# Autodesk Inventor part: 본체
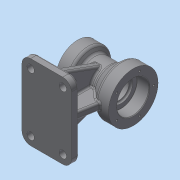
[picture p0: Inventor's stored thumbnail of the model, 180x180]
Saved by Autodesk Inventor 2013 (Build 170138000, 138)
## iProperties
Created: 2015-08
Part Number: 본체
Material: 일반
Document SubType Name: Modeling
Designer: Administrator
Density: 1 g/cm^3
Author: Administrator
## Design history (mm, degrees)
sketch "스케치1"
  geometry: L1 (0, 0)-(90, 0); L2 (0, 0)-(0, 35); L3 (0, 35)-(20, 35); L4 (20, 35)-(25.196, 26); L5 (25.196, 26)-(53.315, 26); L6 (53.315, 26)-(70, 40); L7 (70, 40)-(90, 40); L8 (90, 40)-(90, 0)
  constraints: 17 end point, 3 parallel, 2 perpendicular, 1 horizontal
  dimensions: "d0" = 90 distance of L1.start L1.end; "d2" = 70 diameter of L3 L1; "d3" = 80 diameter of L7 L1; "d4" = 60 deg angle of L5 L4; "d6" = 40 deg angle of L6 L5; "d7" = 20 distance of L6.end L7.end; "d8" = 20 distance of L2.end L3.end; "d9" = 52 diameter of L5 L1
revolve "회전1" sketch "스케치1" stored, may be unused: angle "d10" = 90 deg
node "작업 평면1"
sketch "스케치2"
  geometry: L1 (0, 61)-(80, 61); L2 (80, 61)-(80, -61); L3 (80, -61)-(0, -61); L4 (0, -61)-(0, 61); 2 further points
  constraints: 8 end point, 2 parallel, 1 coincident, 1 horizontal, 1 midpoint, 1 perpendicular, 1 vertical alignment
  dimensions: "d12" = 80 distance of L1.start L1.end; "d14" = 122 distance of L1.end L2.end
extrude "돌출1" join sketch "스케치2" distance "d15" = 12; taper "d16" = 0 deg
fillet "모깎기1" dims "d17" = 14
node "작업 평면2"
sketch "스케치6"
  geometry: L1 (-90, 61)-(-78, 61) reference; L2 (-78, 61)-(-78, -61) reference; L3 (-78, -61)-(-90, -61) reference; L4 (-90, -61)-(-90, 61) reference; L5 (-78, 51)-(-6.815, 25.091); L6 (-6.815, 25.091)-(-6.815, -25.091); L7 (-6.815, -25.091)-(-78, -51); A1 r 26 centre (0, 0) between (-6.815, 25.091) and (-6.815, -25.091) reference; 1 further point
  constraints: 6 end point, 2 point on circle, 2 point on line, 1 parallel
  dimensions: "d29" = 10 distance of L5.start L1.end; "d30" = 10 distance of L2.end L7.end; "d31" = 70 deg angle of L2 L7
extrude "돌출2" join sketch "스케치6" stored distance "d32" = 12; taper "d33" = 0 deg
sketch "스케치7"
  geometry: L1 (0, -35)-(0, 35) reference; L2 (0, 35)-(20, 35) reference; L3 (20, 35)-(25.196, 26) reference; L4 (25.196, 26)-(53.315, 26) reference; L5 (53.315, 26)-(70, 40) reference; L6 (70, 40)-(90, 40) reference; L7 (90, 40)-(90, -40) reference; L8 (90, -40)-(70, -40) reference; L9 (70, -40)-(53.315, -26) reference; L10 (53.315, -26)-(46, -26) reference; L11 (46, -26)-(46, -78) reference; L12 (46, -78)-(80, -78) reference; L13 (80, -78)-(80, -90) reference; L14 (80, -90)-(0, -90) reference; L15 (0, -90)-(0, -78) reference; L16 (0, -78)-(34, -78) reference; L17 (34, -78)-(34, -26) reference; L18 (34, -26)-(25.196, -26) reference; L19 (25.196, -26)-(20, -35) reference; L20 (20, -35)-(0, -35) reference; L21 (10, -35)-(10, -78); L22 (76.7, -40)-(70, -78); 1 further point
  constraints: 4 end point, 3 point on line, 1 midpoint, 1 perpendicular
  dimensions: "d34" = 10 distance from line of L13 L22.end; "d35" = 80 deg angle of L12 L22; "d36" = 10 distance between parallel lines of L21 L15
  node "절단 모서리 투영2"
feature "리브1" dims "d37" = 1, "d38" = 12, "d39" = 0, "d40" = 0, "d41" = 1, "d42" = 1
feature "리브2" dims "d43" = 1, "d44" = 12, "d45" = 0, "d46" = 0, "d47" = 1, "d48" = 1
sketch "스케치8"
  geometry: L1 (-30, -54)-(-30, -60); L2 (-18, -54)-(-18, -60); L3 (-47, -90)-(47, -90) reference; A1 r 26 centre (0, 0) between (-25.091, -6.815) and (-6, -25.298) reference; A2 r 6 centre (-24, -54) between (-18, -54) and (-30, -54); A3 r 6 centre (-24, -60) between (-30, -60) and (-18, -60)
  constraints: 4 end point, 4 point on circle, 4 tangent, 2 centre point, 1 vertical alignment
  dimensions: "d49" = 12 diameter of A2; "d50" = 12 diameter of A3; "d51" = 18 dimension on A3 A2; "d52" = 24 horizontal distance of A1.centre A3.centre; "d53" = 30 distance from line of L3 A3.centre
extrude "돌출3" cut sketch "스케치8" distance "d54" = 12; taper "d55" = 0 deg
sketch "스케치9"
  geometry: C1 r 6 at (14, -47); C2 r 6 at (66, -47); C3 r 6 at (66, 47); C4 r 6 at (14, 47); A1 r 14 centre (66, 47) between (80, 47) and (66, 61) reference; A2 r 14 centre (14, 47) between (14, 61) and (0, 47) reference; A3 r 14 centre (14, -47) between (0, -47) and (14, -61) reference; A4 r 14 centre (66, -47) between (66, -61) and (80, -47) reference; 1 further point
  constraints: 4 centre point, 4 coincident
  dimensions: "d56" = 12 diameter of C1; "d57" = 12 diameter of C2; "d58" = 12 diameter of C3; "d59" = 12 diameter of C4
extrude "돌출4" cut sketch "스케치9" distance "d60" = 12; taper "d61" = 0 deg
hole "구멍1" diameter "d67" = 38; stored, may be unused: countersink angle "d71" = 90 deg, drill point angle "d73" = 0 deg; dims "d65" = 10, "d66" = 10, "d68" = 6, "d69" = 52, "d70" = 20, "d72" = 23
hole "구멍2" diameter "d76" = 32; stored, may be unused: countersink angle "d80" = 90 deg, drill point angle "d82" = 0 deg; dims "d74" = 10, "d75" = 10, "d77" = 6, "d78" = 40, "d79" = 17, "d81" = 23
sketch "스케치11"
  geometry: C1 r 26 at (0, 0) reference; 1 further point
  constraints: 1 vertical alignment
  dimensions: "d83" = 33 distance of C1.centre point (0, 33)
hole "구멍3" sketch "스케치11" at (0, 33) diameter "d84" = 3.242; stored, may be unused: countersink angle "d88" = 90 deg, drill point angle "d90" = 118 deg; dims "d85" = 10, "d86" = 40, "d87" = 17, "d89" = 13
sketch "스케치12"
  geometry: C1 r 20 at (0, 0) reference; 1 further point
  constraints: 1 vertical alignment
  dimensions: "d94" = 27 distance of point (0, 27) C1.centre
hole "구멍4" sketch "스케치12" at (0, 27) diameter "d95" = 3.242; stored, may be unused: countersink angle "d99" = 90 deg, drill point angle "d101" = 118 deg; dims "d96" = 10, "d97" = 40, "d98" = 17, "d100" = 13
fillet "모깎기2" dims "d105" = 5
fillet "모깎기3" dims "d106" = 0.3
fillet "모깎기4" dims "d107" = 3
fillet "모깎기5" dims "d108" = 3
chamfer "모따기1" distance "d109" = 1; stored, may be unused: second distance "d110" = 2, angle "d111" = 45 deg
sketch "스케치14"
  geometry: L1 (-3, 37.119)-(-3, 0) reference; L2 (53, -3)-(1, -3) reference; 2 further points
  constraints: 1 other
  dimensions: "d112" = 16 distance from line of L1 point (13, 21); "d113" = 24 distance from line of point (13, 21) L2
feature "엠보싱1" sketch "스케치14" dims "d0" = 90, "d2" = 70, "d3" = 80, "d4" = 60 deg, "d6" = 40 deg, "d7" = 20, "d8" = 20, "d9" = 52, "d114" = 0.5, "d115" = 0
sketch "스케치15"
  geometry: 1 further point
node "솔리드1"
mirror "대칭1"
pattern_circular "원형 패턴1" dims angle "d92" = 360 deg
pattern_circular "원형 패턴2" dims angle "d103" = 360 deg
node "절단 모서리 투영1"
